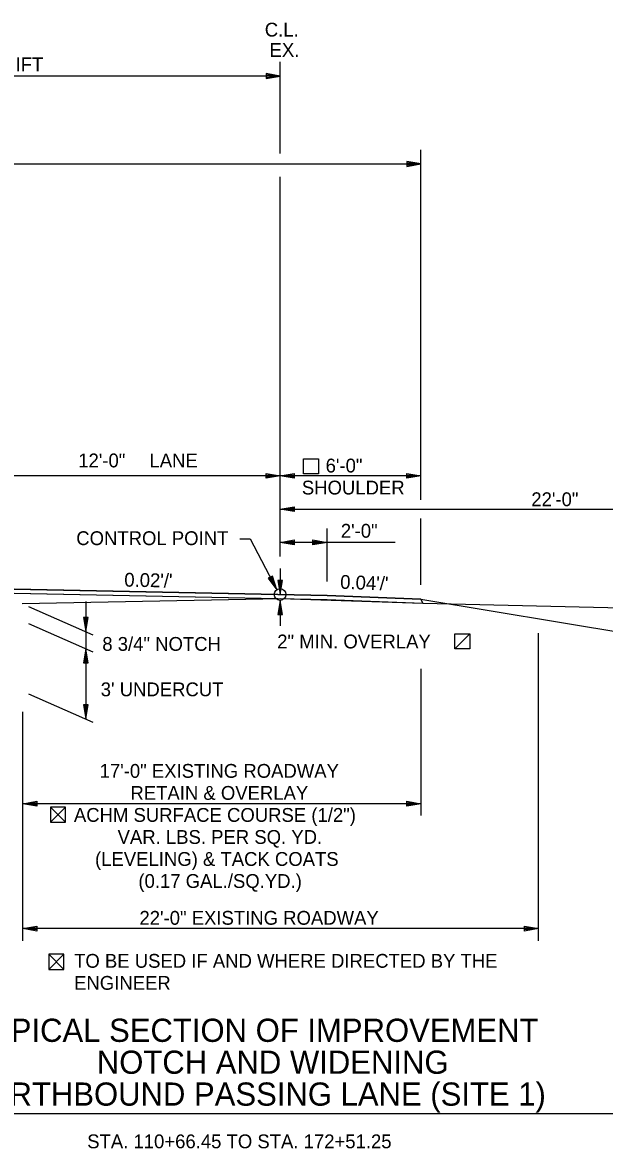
# Model space of a CAD drawing. Extents: x 1398565 to 1398920, y 1968324 to 1968581.
# Drawn here: x 1398642.81 to 1398667.63, y 1968479.81 to 1968527.87 of the extents above; entities that cross this region are included whole.
import ezdxf

# ---------------------------------------------------------------- set-up
doc = ezdxf.new("R2010")
doc.units = 0
for name, color, linetype in [('10', 7, 'Continuous'), ('19', 7, 'Continuous'), ('42', 7, 'Continuous'), ('7', 7, 'Continuous'), ('Level 9', 7, 'Continuous')]:
    doc.layers.add(name, color=color, linetype=linetype)

msp = doc.modelspace()

# ---------------------------------------------------------------- linework, layer by layer
at = {"layer": '10'}
for p, q in [((1398643.998, 1968494.379), (1398644.64, 1968493.737)), ((1398644.64, 1968494.379), (1398643.998, 1968493.737)), ((1398644.38, 1968493.737), (1398644.391, 1968493.737)), ((1398643.935, 1968488.099), (1398644.576, 1968487.458)), ((1398644.576, 1968488.099), (1398643.935, 1968487.458)), ((1398644.316, 1968487.458), (1398644.327, 1968487.458))]:
    msp.add_line(p, q, dxfattribs=at)
for points in [[(1398654.785, 1968509.254), (1398655.426, 1968509.254), (1398655.426, 1968508.613), (1398654.785, 1968508.613)], [(1398661.246, 1968501.774), (1398661.888, 1968501.774), (1398661.888, 1968501.133), (1398661.246, 1968501.133)], [(1398661.246, 1968501.774), (1398661.888, 1968501.774), (1398661.246, 1968501.133)]]:
    msp.add_lwpolyline(points, close=True, dxfattribs=at)
for points in [[(1398644.391, 1968493.737), (1398644.64, 1968493.737), (1398644.64, 1968494.379), (1398643.998, 1968494.379), (1398643.998, 1968493.737), (1398644.38, 1968493.737)], [(1398644.327, 1968487.458), (1398644.576, 1968487.458), (1398644.576, 1968488.099), (1398643.935, 1968488.099), (1398643.935, 1968487.458), (1398644.316, 1968487.458)]]:
    msp.add_lwpolyline(points, dxfattribs=at)
at = {"layer": '19'}
for p, q in [((1398653.195, 1968525.69), (1398653.195, 1968525.48)), ((1398653.795, 1968525.585), (1398653.195, 1968525.69)), ((1398653.795, 1968525.585), (1398629.795, 1968525.585)), ((1398653.635, 1968525.6), (1398653.195, 1968525.635)), ((1398653.195, 1968525.48), (1398653.795, 1968525.585)), ((1398653.195, 1968525.53), (1398653.635, 1968525.57)), ((1398659.795, 1968507.493), (1398659.795, 1968522.435)), ((1398609.795, 1968521.835), (1398659.795, 1968521.835)), ((1398659.195, 1968521.94), (1398659.195, 1968521.73)), ((1398659.795, 1968521.835), (1398659.195, 1968521.94)), ((1398659.635, 1968521.85), (1398659.195, 1968521.885)), ((1398659.195, 1968521.73), (1398659.795, 1968521.835)), ((1398659.195, 1968521.78), (1398659.635, 1968521.82)), ((1398643.795, 1968508.52), (1398631.795, 1968508.52)), ((1398659.795, 1968508.52), (1398643.795, 1968508.52)), ((1398653.195, 1968508.415), (1398653.195, 1968508.625)), ((1398653.195, 1968508.625), (1398653.795, 1968508.52)), ((1398653.195, 1968508.57), (1398653.635, 1968508.535)), ((1398653.795, 1968508.52), (1398653.195, 1968508.415)), ((1398653.635, 1968508.505), (1398653.195, 1968508.465)), ((1398653.795, 1968508.52), (1398654.395, 1968508.625)), ((1398654.395, 1968508.415), (1398653.795, 1968508.52)), ((1398653.955, 1968508.535), (1398654.395, 1968508.57)), ((1398654.395, 1968508.465), (1398653.955, 1968508.505)), ((1398654.395, 1968508.625), (1398654.395, 1968508.415)), ((1398659.195, 1968508.415), (1398659.195, 1968508.625)), ((1398659.195, 1968508.625), (1398659.795, 1968508.52)), ((1398659.195, 1968508.57), (1398659.635, 1968508.535)), ((1398659.795, 1968508.52), (1398659.195, 1968508.415)), ((1398659.635, 1968508.505), (1398659.195, 1968508.465)), ((1398653.795, 1968507.099), (1398654.395, 1968507.204)), ((1398653.795, 1968507.099), (1398675.795, 1968507.099)), ((1398654.395, 1968506.994), (1398653.795, 1968507.099)), ((1398653.955, 1968507.114), (1398654.395, 1968507.149)), ((1398654.395, 1968507.044), (1398653.955, 1968507.084)), ((1398654.395, 1968507.204), (1398654.395, 1968506.994)), ((1398659.795, 1968503.865), (1398659.795, 1968506.707)), ((1398655.795, 1968504.016), (1398655.795, 1968506.278)), ((1398653.795, 1968505.678), (1398654.395, 1968505.783)), ((1398658.699, 1968505.678), (1398653.795, 1968505.678)), ((1398654.395, 1968505.573), (1398653.795, 1968505.678)), ((1398653.955, 1968505.693), (1398654.395, 1968505.728)), ((1398654.395, 1968505.623), (1398653.955, 1968505.663)), ((1398654.395, 1968505.783), (1398654.395, 1968505.573)), ((1398655.195, 1968505.573), (1398655.195, 1968505.783)), ((1398655.195, 1968505.783), (1398655.795, 1968505.678)), ((1398655.195, 1968505.728), (1398655.635, 1968505.693)), ((1398655.795, 1968505.678), (1398655.195, 1968505.573)), ((1398655.635, 1968505.663), (1398655.195, 1968505.623)), ((1398653.795, 1968504.565), (1398653.795, 1968503.456)), ((1398653.472, 1968504.242), (1398653.286, 1968504.147)), ((1398653.286, 1968504.147), (1398653.649, 1968503.659)), ((1398653.328, 1968504.165), (1398653.563, 1968503.796)), ((1398653.587, 1968503.806), (1398653.426, 1968504.213)), ((1398653.649, 1968503.659), (1398653.472, 1968504.242)), ((1398653.9, 1968504.056), (1398653.69, 1968504.056)), ((1398653.69, 1968504.056), (1398653.795, 1968503.456)), ((1398653.745, 1968504.056), (1398653.78, 1968503.616)), ((1398653.795, 1968503.456), (1398653.9, 1968504.056)), ((1398653.81, 1968503.616), (1398653.85, 1968504.056)), ((1398629.795, 1968503.936), (1398655.795, 1968503.416)), ((1398629.795, 1968503.77), (1398655.795, 1968503.25)), ((1398645.508, 1968503.152), (1398645.508, 1968501.876)), ((1398653.795, 1968503.206), (1398653.69, 1968502.606)), ((1398653.9, 1968502.606), (1398653.795, 1968503.206)), ((1398653.795, 1968503.206), (1398653.795, 1968502.124)), ((1398655.795, 1968503.416), (1398659.795, 1968503.256)), ((1398655.795, 1968503.25), (1398659.88, 1968503.086)), ((1398659.795, 1968503.256), (1398675.795, 1968500.59)), ((1398659.795, 1968503.256), (1398659.88, 1968503.086)), ((1398643.068, 1968502.949), (1398645.81, 1968501.739)), ((1398653.69, 1968502.606), (1398653.9, 1968502.606)), ((1398653.78, 1968503.046), (1398653.745, 1968502.606)), ((1398653.85, 1968502.606), (1398653.81, 1968503.046)), ((1398643.068, 1968502.22), (1398645.81, 1968501.01)), ((1398645.613, 1968502.476), (1398645.403, 1968502.476)), ((1398645.403, 1968502.476), (1398645.508, 1968501.876)), ((1398645.458, 1968502.476), (1398645.493, 1968502.036)), ((1398645.508, 1968501.876), (1398645.613, 1968502.476)), ((1398645.523, 1968502.036), (1398645.563, 1968502.476)), ((1398645.508, 1968501.876), (1398645.508, 1968498.144)), ((1398664.818, 1968488.68), (1398664.818, 1968501.811)), ((1398645.508, 1968501.144), (1398645.403, 1968500.544)), ((1398645.493, 1968500.984), (1398645.458, 1968500.544)), ((1398645.613, 1968500.544), (1398645.508, 1968501.144)), ((1398645.563, 1968500.544), (1398645.523, 1968500.984)), ((1398645.403, 1968500.544), (1398645.613, 1968500.544)), ((1398659.795, 1968500.279), (1398659.795, 1968494.029)), ((1398643.068, 1968499.22), (1398645.81, 1968498.01)), ((1398642.818, 1968488.68), (1398642.818, 1968498.451)), ((1398645.613, 1968498.744), (1398645.403, 1968498.744)), ((1398645.403, 1968498.744), (1398645.508, 1968498.144)), ((1398645.458, 1968498.744), (1398645.493, 1968498.304)), ((1398645.508, 1968498.144), (1398645.613, 1968498.744)), ((1398645.523, 1968498.304), (1398645.563, 1968498.744)), ((1398642.818, 1968494.525), (1398643.418, 1968494.63)), ((1398643.418, 1968494.42), (1398642.818, 1968494.525)), ((1398659.795, 1968494.525), (1398642.818, 1968494.525)), ((1398642.978, 1968494.54), (1398643.418, 1968494.575)), ((1398643.418, 1968494.47), (1398642.978, 1968494.51)), ((1398643.418, 1968494.63), (1398643.418, 1968494.42)), ((1398659.195, 1968494.42), (1398659.195, 1968494.63)), ((1398659.195, 1968494.63), (1398659.795, 1968494.525)), ((1398659.195, 1968494.575), (1398659.635, 1968494.54)), ((1398659.795, 1968494.525), (1398659.195, 1968494.42)), ((1398659.635, 1968494.51), (1398659.195, 1968494.47)), ((1398642.818, 1968489.199), (1398643.418, 1968489.304)), ((1398664.818, 1968489.199), (1398642.818, 1968489.199)), ((1398643.418, 1968489.094), (1398642.818, 1968489.199)), ((1398642.978, 1968489.214), (1398643.418, 1968489.249)), ((1398643.418, 1968489.144), (1398642.978, 1968489.184)), ((1398643.418, 1968489.304), (1398643.418, 1968489.094)), ((1398664.218, 1968489.094), (1398664.218, 1968489.304)), ((1398664.218, 1968489.304), (1398664.818, 1968489.199)), ((1398664.218, 1968489.249), (1398664.658, 1968489.214)), ((1398664.818, 1968489.199), (1398664.218, 1968489.094)), ((1398664.658, 1968489.184), (1398664.218, 1968489.144)), ((1398639.176, 1968481.304), (1398668.156, 1968481.304))]:
    msp.add_line(p, q, dxfattribs=at)
msp.add_lwpolyline([(1398652.07, 1968505.837), (1398652.516, 1968505.837), (1398653.649, 1968503.659)], dxfattribs=at)
msp.add_lwpolyline([(1398609.712, 1968503.251), (1398615.795, 1968503.49), (1398629.795, 1968503.77), (1398655.795, 1968503.25), (1398659.88, 1968503.086), (1398659.795, 1968503.256), (1398655.795, 1968503.416), (1398629.795, 1968503.936), (1398615.795, 1968503.656), (1398609.795, 1968503.416)], close=True, dxfattribs=at)
at = {"layer": '42'}
for points in [[(1398642.795, 1968503.07), (1398653.795, 1968503.29)], [(1398653.795, 1968503.29), (1398659.88, 1968503.086), (1398670.795, 1968502.83), (1398679.65, 1968500.369), (1398684.731, 1968500.911), (1398701.547, 1968500.822)]]:
    msp.add_lwpolyline(points, dxfattribs=at)
at = {"layer": '7'}
for p, q in [((1398653.795, 1968522.283), (1398653.795, 1968526.185)), ((1398653.795, 1968505.073), (1398653.795, 1968521.28))]:
    msp.add_line(p, q, dxfattribs=at)
at = {"layer": 'Level 9'}
msp.add_circle((1398653.795, 1968503.456), 0.25, dxfattribs=at)

# ---------------------------------------------------------------- texts
at = {"layer": '10'}
for s, height, p in [('12\'-0" ', 0.59, (1398645.183, 1968508.883)), ('LANE', 0.59, (1398648.221, 1968508.883)), ('6\'-0" ', 0.59, (1398655.735, 1968508.665)), ('SHOULDER', 0.59, (1398654.722, 1968507.725)), ('22\'-0"', 0.59, (1398664.509, 1968507.227)), ('2\'-0"', 0.59, (1398656.383, 1968505.881)), ('CONTROL POINT', 0.59001, (1398645.099, 1968505.565)), ('8 3/4" NOTCH', 0.59001, (1398646.21, 1968501.052)), ('2" MIN. OVERLAY', 0.59001, (1398653.671, 1968501.156)), ("3' UNDERCUT", 0.59001, (1398646.143, 1968499.113)), ('17\'-0" EXISTING ROADWAY', 0.59001, (1398646.095, 1968495.633)), ('RETAIN & OVERLAY', 0.59001, (1398647.41, 1968494.693)), ('ACHM SURFACE COURSE (1/2")', 0.59001, (1398644.999, 1968493.753)), ('VAR. LBS. PER SQ. YD.', 0.59001, (1398646.862, 1968492.813)), ('(LEVELING) & TACK COATS', 0.59001, (1398645.9, 1968491.873)), ('(0.17 GAL./SQ.YD.)', 0.59001, (1398647.749, 1968490.933)), ('22\'-0" EXISTING ROADWAY', 0.59001, (1398647.794, 1968489.361)), ('TO BE USED IF AND WHERE DIRECTED BY THE ', 0.59001, (1398645.007, 1968487.525)), ('ENGINEER', 0.59, (1398645.007, 1968486.585)), ('STA. 110+66.45 TO STA. 172+51.25', 0.59001, (1398645.566, 1968479.821))]:
    msp.add_text(s, height=height, rotation=360, dxfattribs=at).set_placement(p)
at = {"layer": '19'}
msp.add_text('C.L.', height=0.59, dxfattribs=at).set_placement((1398653.14, 1968527.271))
for s, height, rotation, p in [('EX.', 0.59, 360, (1398653.345, 1968526.403)), ("24' SHIFT", 0.59, 360, (1398640.167, 1968525.792)), ("0.02'/'", 0.59, 358.8542, (1398647.143, 1968503.795)), ("0.04'/'", 0.59, 357.7094, (1398656.347, 1968503.706)), ('TYPICAL SECTION OF IMPROVEMENT', 0.98999, 360, (1398640.613, 1968484.362)), ('NOTCH AND WIDENING', 0.98999, 360, (1398645.976, 1968483)), ('NORTHBOUND PASSING LANE (SITE 1)', 0.98999, 360, (1398640.266, 1968481.639))]:
    msp.add_text(s, height=height, rotation=rotation, dxfattribs=at).set_placement(p)

doc.saveas('drawing.dxf')
